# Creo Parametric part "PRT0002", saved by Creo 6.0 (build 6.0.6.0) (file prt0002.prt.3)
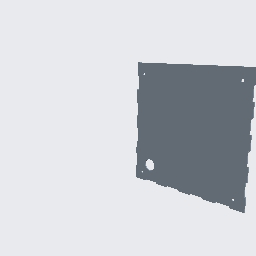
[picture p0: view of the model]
Units: Inch lbm Second (Pro/E Default); INCH, POUND, SECS

Created from: INLBS_PART_SOLID.PRT

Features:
  1. datum plane "RIGHT"
  2. datum plane "TOP"
  3. datum plane "FRONT"
  4. coordinate system
  5. sketch "Sketch 1"
  6. extrusion "Extrude 1"
  7. sketch "Sketch 2"
  8. extruded cut "Extrude 2"
  9. sketch "Sketch 3"
  10. extruded cut "Extrude 3"

Surfaces: 54 plane, 5 cylinder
